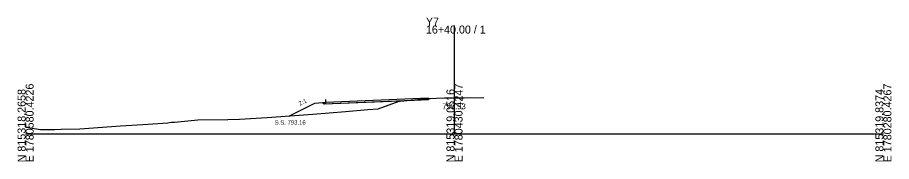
# Model space of a CAD drawing. Extents: x -26 to 2903, y -10 to 5536.
# Drawn here: x 1297.2 to 1602.8, y 990.3 to 1040.5 of the extents above; entities that cross this region are included whole.
import ezdxf

# ---------------------------------------------------------------- set-up
doc = ezdxf.new("R2010")
doc.units = 0
for name, color, linetype in [('Exist Cross Section Cell', 7, 'Continuous'), ('Exist XS Center Line Elevation Label', 7, 'Continuous'), ('Exist XS Ground Line', 7, 'Continuous'), ('Prop XS Dump Level', 7, 'Continuous'), ('Prop XS Earthwork Shape', 7, 'Continuous'), ('Prop XS EOT Tick Mark', 7, 'Continuous'), ('Prop XS Finish Grade', 7, 'Continuous'), ('Prop XS Finish Grade Earthwork', 7, 'Continuous'), ('Prop XS Finish Grade Pavement', 7, 'Continuous'), ('Prop XS Pvmt Edge Slope', 7, 'Continuous'), ('Prop XS Side Slope Text', 7, 'Continuous'), ('Prop XS SS Elevation Text', 7, 'Continuous'), ('Prop XS Subgrade Earthwork', 7, 'Continuous')]:
    doc.layers.add(name, color=color, linetype=linetype)

msp = doc.modelspace()

# ---------------------------------------------------------------- linework, layer by layer
at = {"layer": 'Exist Cross Section Cell'}
for p, q in [((1450, 1000), (1450, 1037.74)), ((1300, 1000), (1450, 1000)), ((1450, 1000), (1600, 1000))]:
    msp.add_line(p, q, dxfattribs=at)
at = {"layer": 'Exist XS Ground Line'}
for p, q in [((1430.94, 1011.4), (1440.9, 1012.24)), ((1440.9, 1012.24), (1446.47, 1012.46)), ((1446.47, 1012.46), (1449.38, 1012.53)), ((1449.38, 1012.53), (1450, 1012.53)), ((1450, 1012.53), (1453.42, 1012.56)), ((1453.42, 1012.56), (1460.31, 1012.58)), ((1423.33, 1008.65), (1430.61, 1011.31)), ((1430.61, 1011.31), (1430.94, 1011.4)), ((1374.8, 1005.07), (1384.48, 1005.7)), ((1384.48, 1005.7), (1392.44, 1006.18)), ((1392.44, 1006.18), (1400.44, 1006.8)), ((1400.44, 1006.8), (1411.84, 1007.7)), ((1411.84, 1007.7), (1419.64, 1008.4)), ((1419.64, 1008.4), (1423.33, 1008.65)), ((1318.96, 1001.67), (1333.21, 1002.78)), ((1333.21, 1002.78), (1340.95, 1003.26)), ((1340.95, 1003.26), (1349.69, 1003.84)), ((1349.69, 1003.84), (1351.05, 1003.98)), ((1351.05, 1003.98), (1352.02, 1004.07)), ((1352.02, 1004.07), (1360.23, 1004.8)), ((1360.23, 1004.8), (1370.71, 1004.99)), ((1370.71, 1004.99), (1374.8, 1005.07)), ((1300, 1002.24), (1301.64, 1001.99)), ((1301.64, 1001.99), (1305.22, 1001.42)), ((1305.22, 1001.42), (1306.63, 1001.42)), ((1306.63, 1001.42), (1308.35, 1001.48)), ((1308.35, 1001.48), (1310.27, 1001.52)), ((1310.27, 1001.52), (1312.48, 1001.62)), ((1312.48, 1001.62), (1318.96, 1001.67))]:
    msp.add_line(p, q, dxfattribs=at)
at = {"layer": 'Prop XS Earthwork Shape'}
for points in [[(1430.84, 1011.37), (1430.94, 1011.4), (1440.9, 1012.24), (1440.91, 1012.24), (1440.91, 1011.78)], [(1401, 1010.58), (1392.17, 1006.16), (1392.44, 1006.18), (1400.44, 1006.8), (1411.84, 1007.7), (1419.64, 1008.4), (1423.33, 1008.65), (1430.61, 1011.31), (1430.84, 1011.37), (1404.39, 1010.29), (1403.87, 1010.81)]]:
    msp.add_lwpolyline(points, close=True, dxfattribs=at)
at = {"layer": 'Prop XS EOT Tick Mark'}
for p, q in [((1405, 1010.9), (1405, 1011.9)), ((1450, 1000), (1450, 1001))]:
    msp.add_line(p, q, dxfattribs=at)
at = {"layer": 'Prop XS Finish Grade'}
msp.add_line((1405, 1010.9), (1403.87, 1010.81), dxfattribs=at)
at = {"layer": 'Prop XS Finish Grade Earthwork'}
for p, q in [((1401, 1010.58), (1392.17, 1006.16)), ((1403.87, 1010.81), (1401, 1010.58))]:
    msp.add_line(p, q, dxfattribs=at)
at = {"layer": 'Prop XS Finish Grade Pavement'}
for q in [(1405, 1010.9), (1440.93, 1012.24)]:
    msp.add_line((1440.91, 1012.36), q, dxfattribs=at)
at = {"layer": 'Prop XS Pvmt Edge Slope'}
msp.add_line((1405, 1010.9), (1404.39, 1010.29), dxfattribs=at)
at = {"layer": 'Prop XS Subgrade Earthwork'}
for p, q in [((1440.91, 1011.78), (1440.91, 1012.24)), ((1404.39, 1010.29), (1403.87, 1010.81)), ((1440.91, 1011.78), (1404.39, 1010.29))]:
    msp.add_line(p, q, dxfattribs=at)

# ---------------------------------------------------------------- texts
at = {"layer": 'Exist Cross Section Cell'}
for s, p in [('Y7', (1440, 1037.74)), ('16+40.00 / 1', (1440, 1034.94))]:
    msp.add_text(s, height=2.8, dxfattribs=at).set_placement(p)
for s, p in [('N 815318.2658', (1300, 990)), ('E 1780580.4226', (1302.8, 990)), ('N 815319.0516', (1450, 990)), ('E 1780430.4247', (1452.8, 990)), ('N 815319.8374', (1600, 990)), ('E 1780280.4267', (1602.8, 990))]:
    msp.add_text(s, height=2.8, rotation=90, dxfattribs=at).set_placement(p)
at = {"layer": 'Exist XS Center Line Elevation Label'}
msp.add_text('799.53', height=2, dxfattribs=at).set_placement((1445.75, 1008.53))
at = {"layer": 'Prop XS Dump Level'}
for s, height, p in [('Eop', 0.3, (1440.91, 1011.94)), ('Case1', 0.04, (1401, 1010.54))]:
    msp.add_text(s, height=height, dxfattribs=at).set_placement(p)
at = {"layer": 'Prop XS Side Slope Text'}
msp.add_text('2:1', height=1.5, rotation=26.5651, dxfattribs=at).set_placement((1395.91, 1009.71))
at = {"layer": 'Prop XS SS Elevation Text'}
msp.add_text('S.S. 793.16', height=1.5, dxfattribs=at).set_placement((1387.12, 1003.16))

doc.saveas('drawing.dxf')
